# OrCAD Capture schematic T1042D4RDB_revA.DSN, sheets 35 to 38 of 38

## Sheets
35 35 Pwr Switch: size B
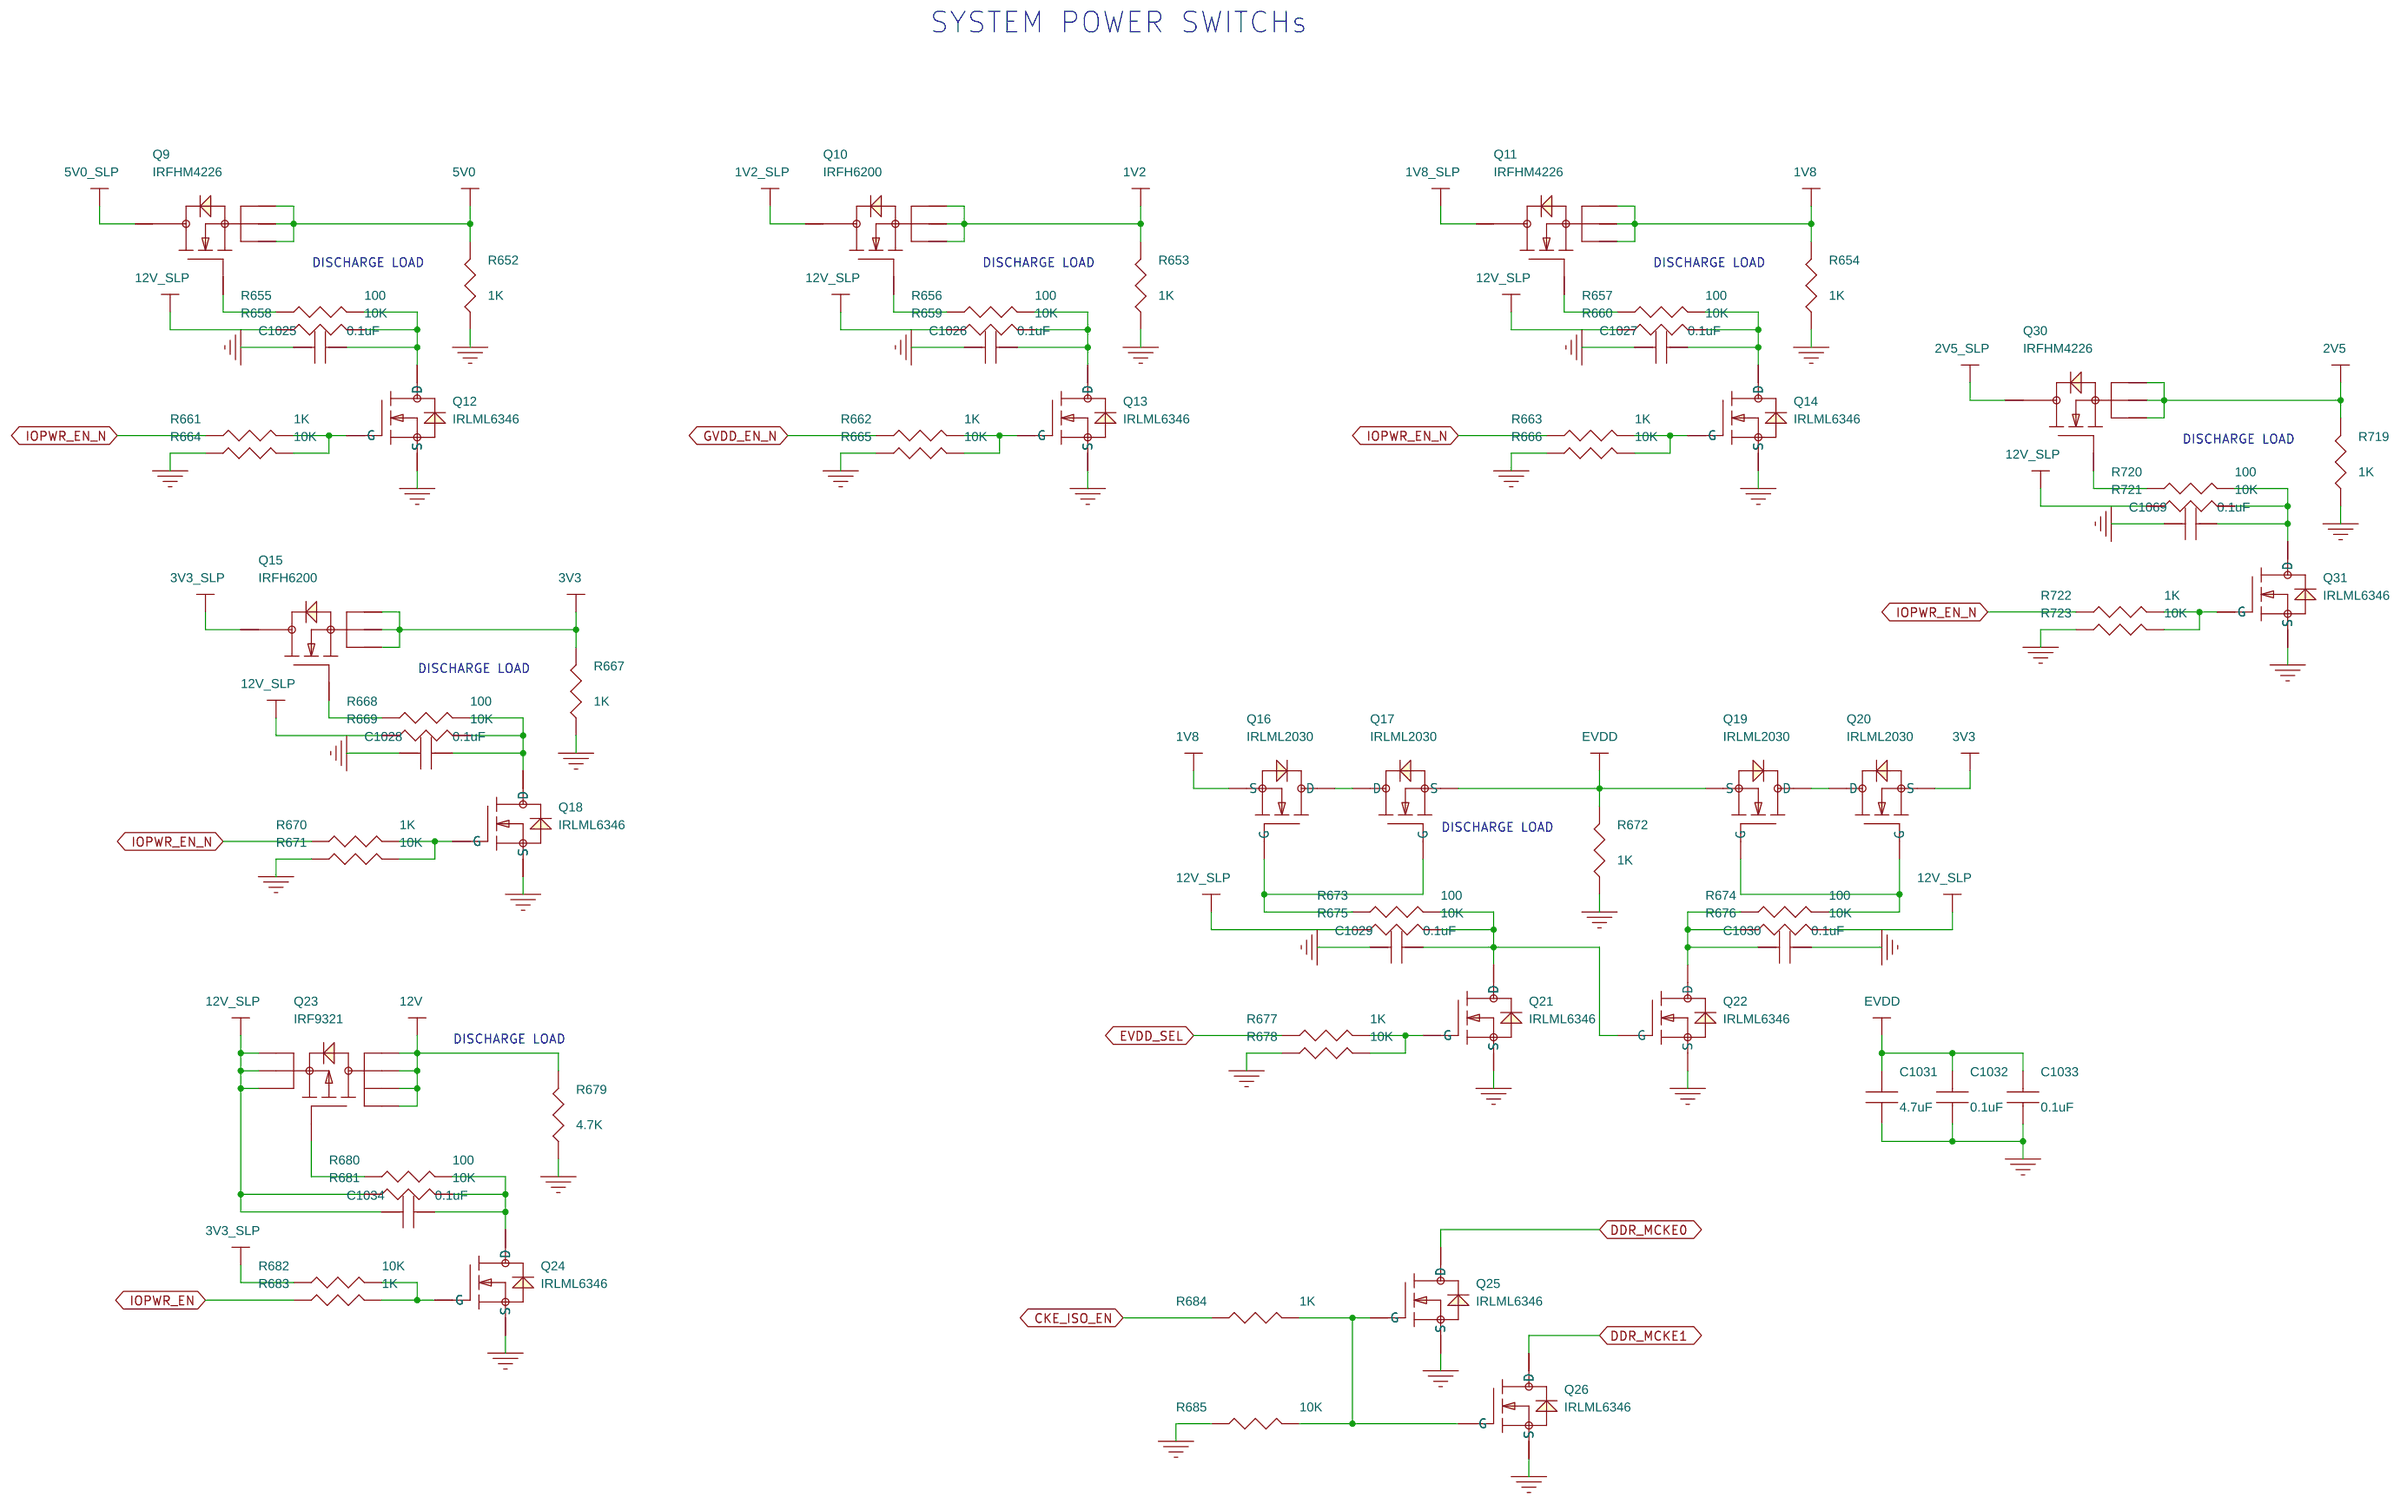
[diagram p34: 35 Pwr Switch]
36 36 Pwr In: size B
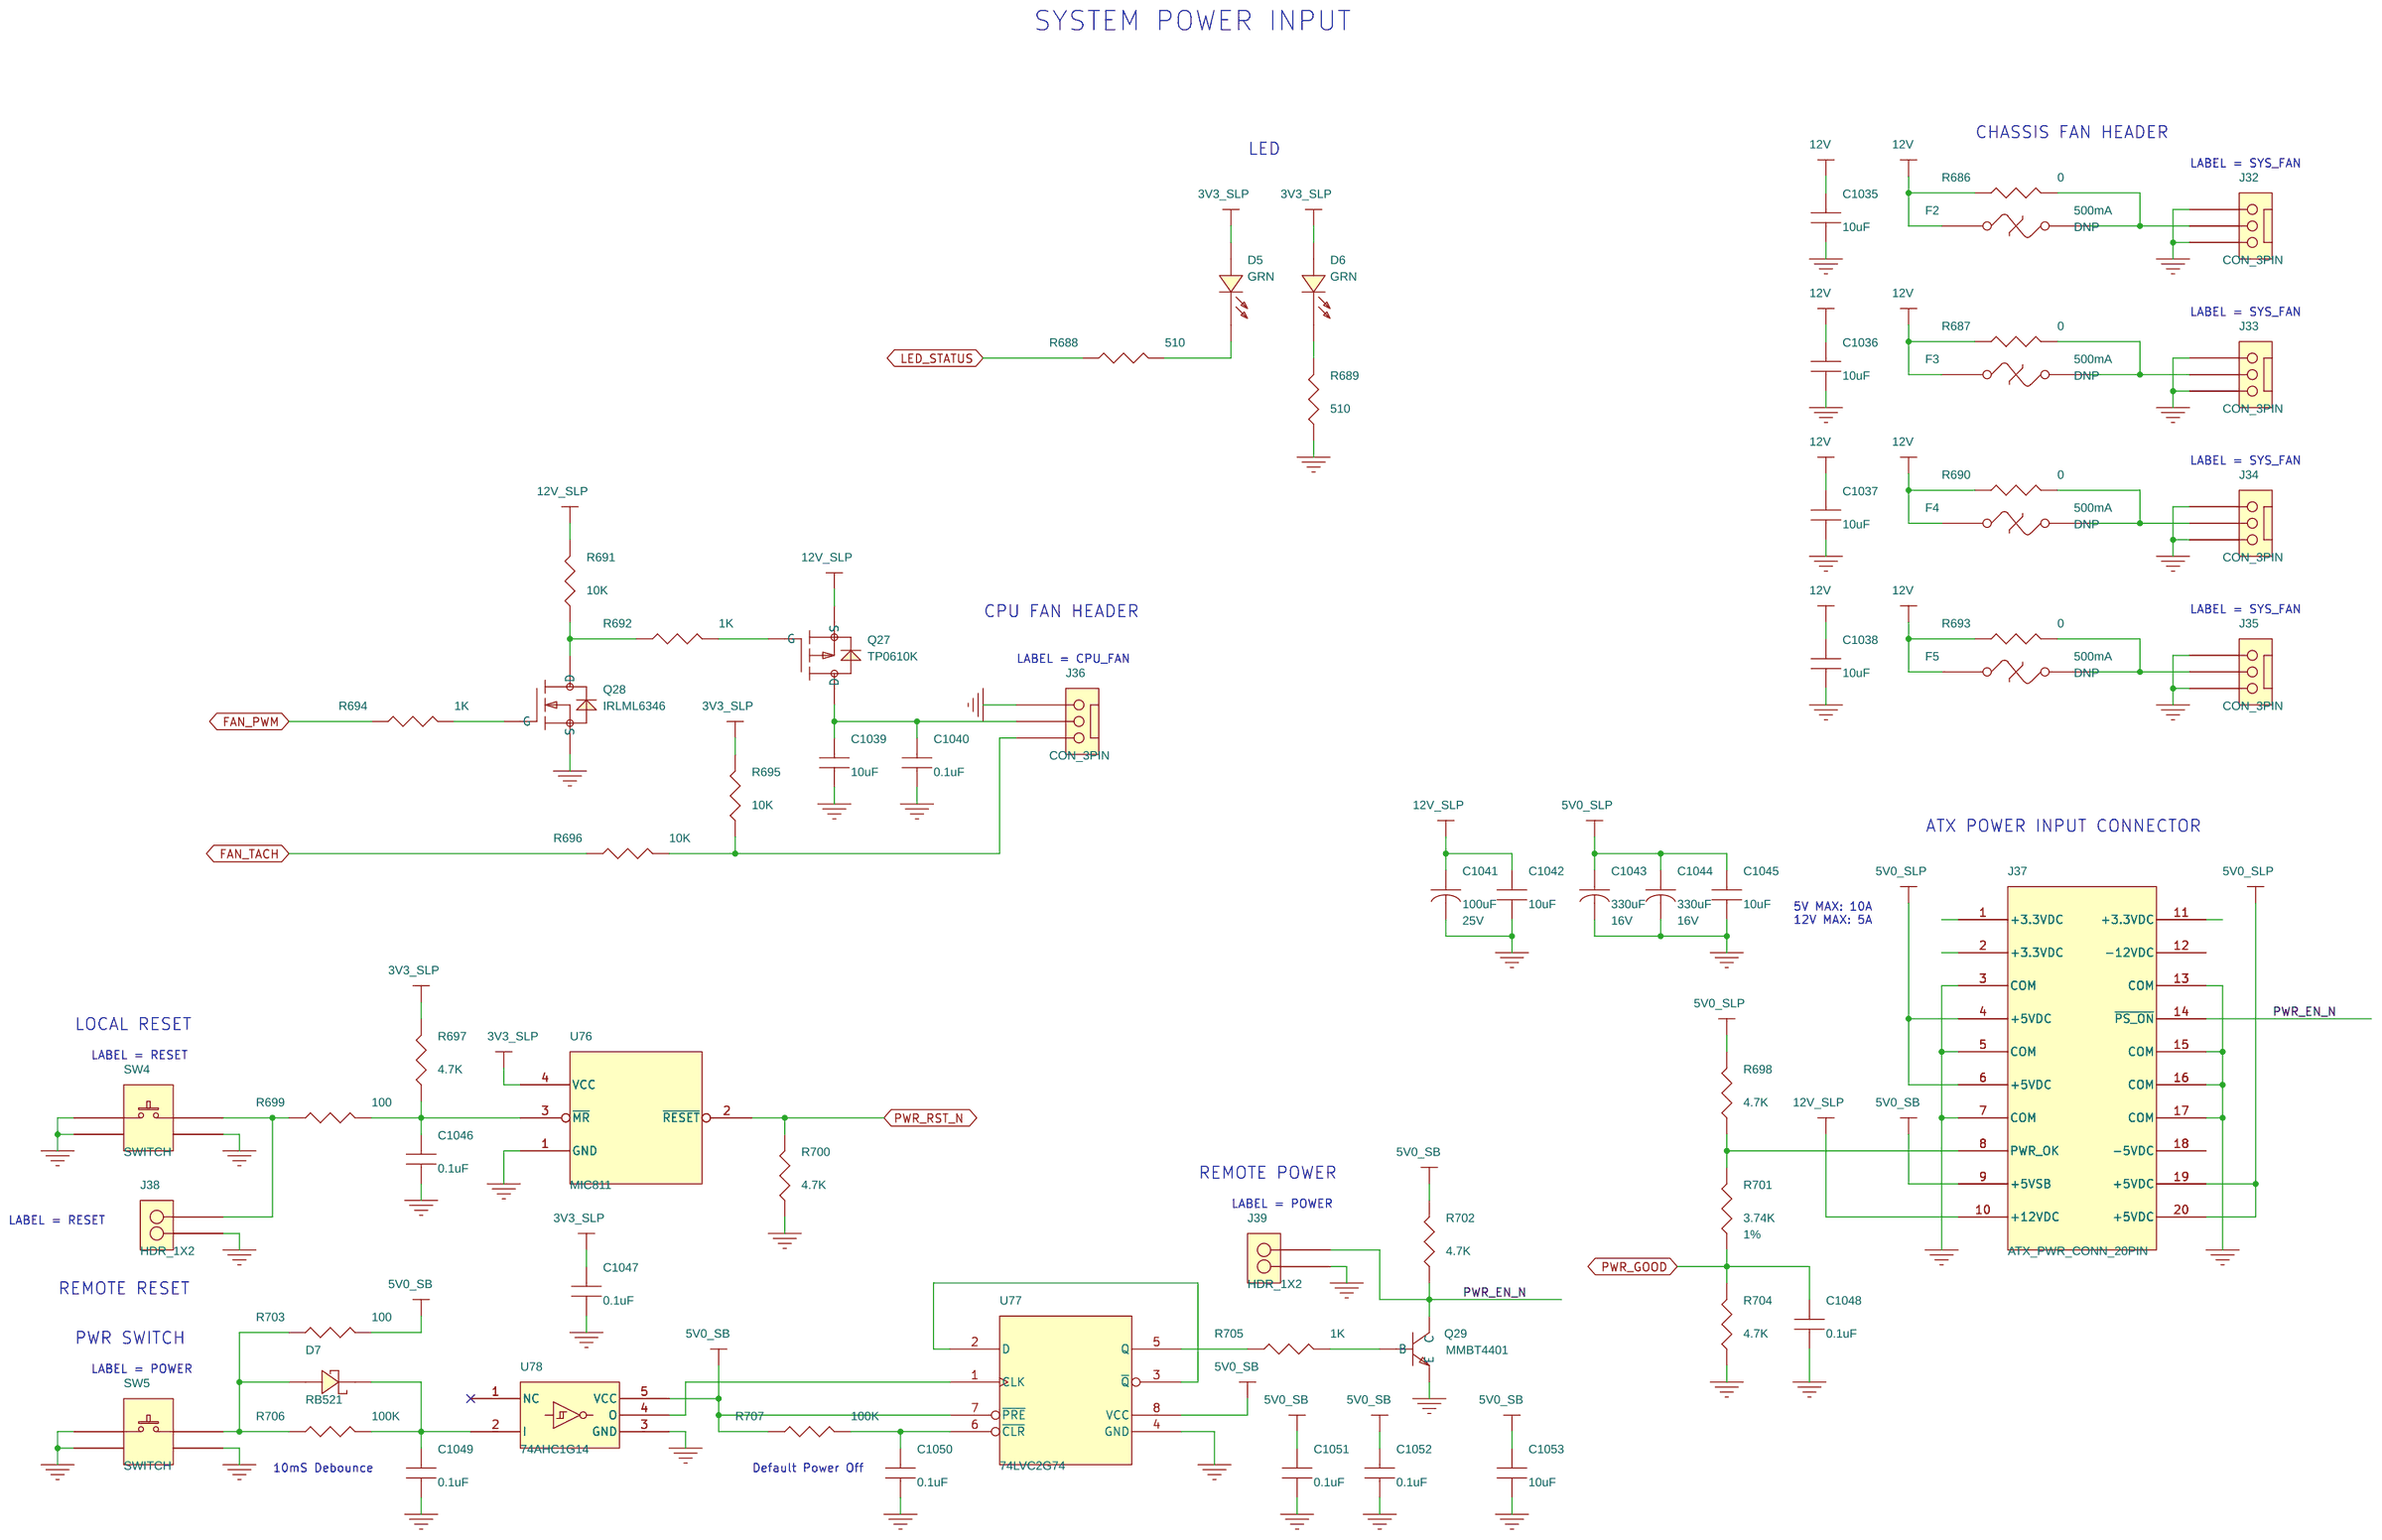
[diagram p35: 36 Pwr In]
37 37 MEC: size B
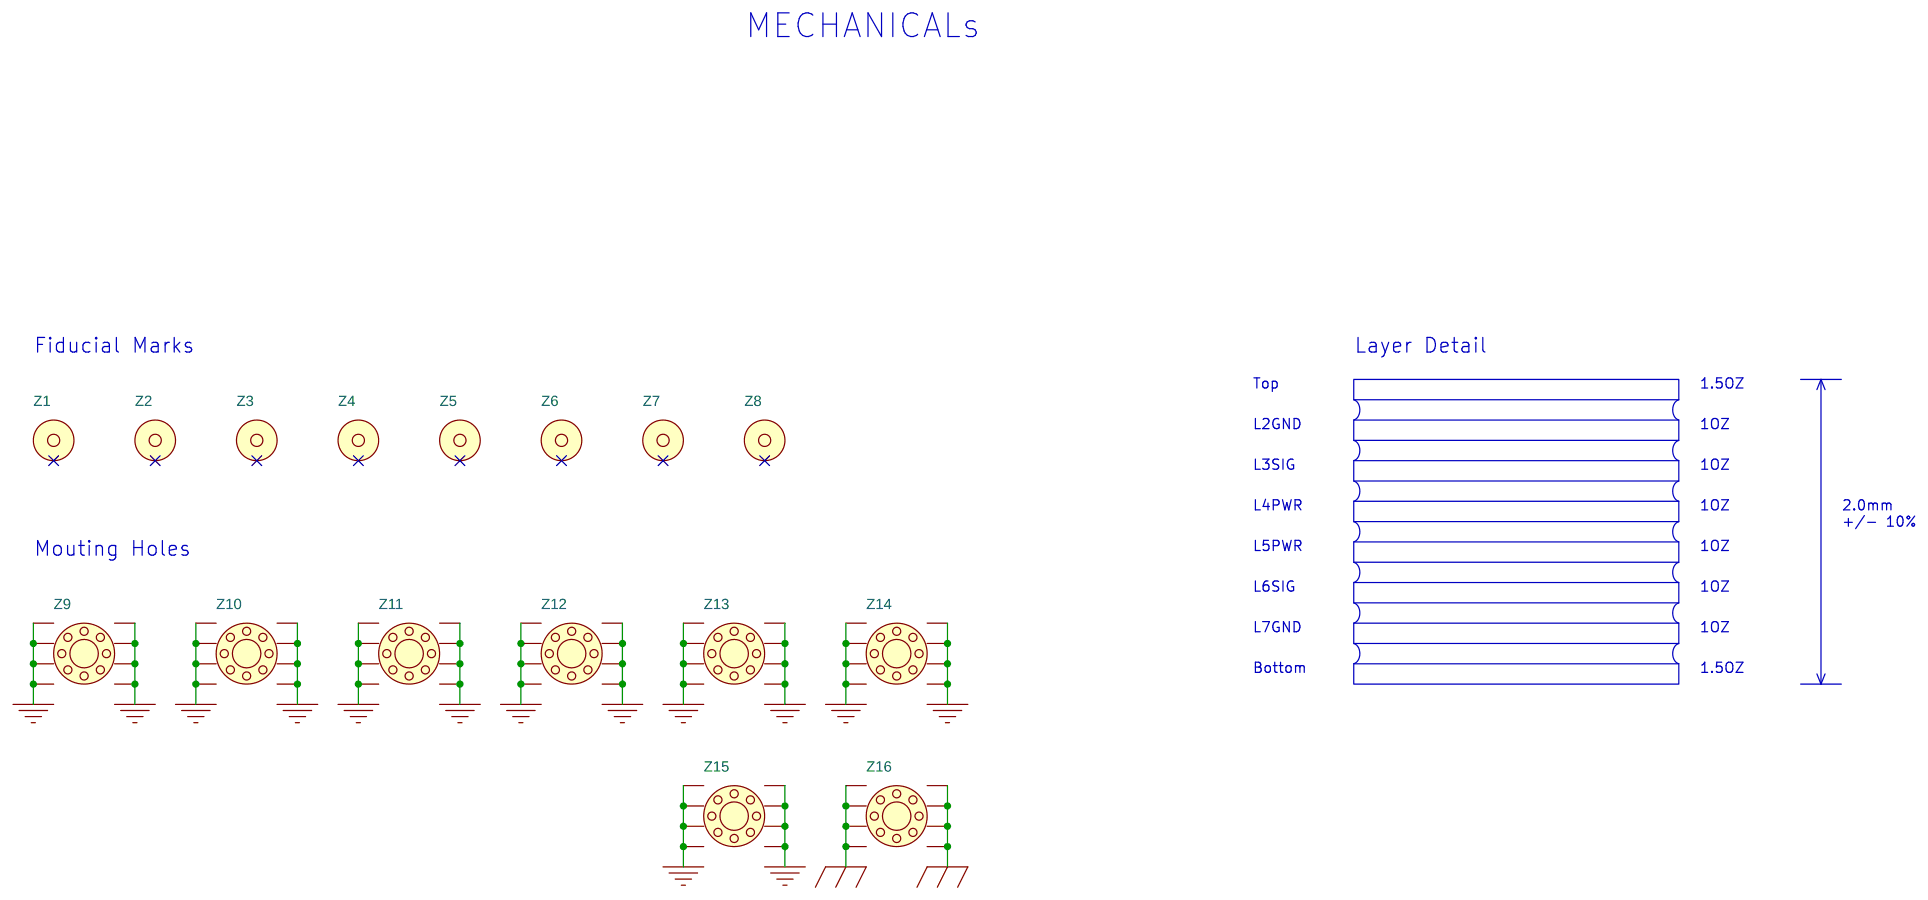
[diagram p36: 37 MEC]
38 38 Change List
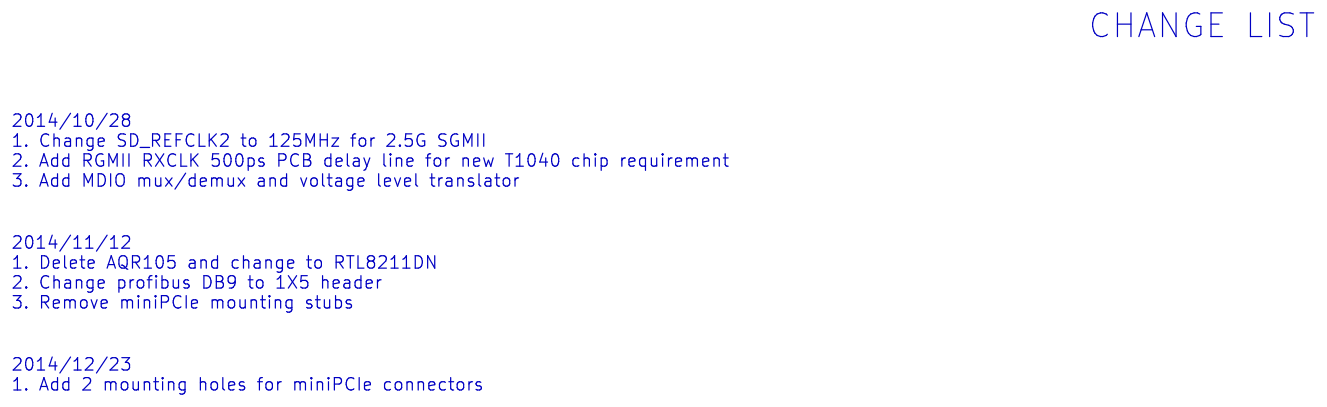
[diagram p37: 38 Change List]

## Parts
sheet 35 Pwr Switch
C1025  0.1uF  [0402]
C1026  0.1uF  [0402]
C1027  0.1uF  [0402]
C1028  0.1uF  [0402]
C1029  0.1uF  [0402]
C1030  0.1uF  [0402]
C1031  4.7uF  [0603]
C1032  0.1uF  [0402]
C1033  0.1uF  [0402]
C1034  0.1uF  [0402]
C1069  0.1uF  [0402]
Q9  IRFHM4226  [u8_fl]
Q10  IRFH6200  [so_8_fl]
Q11  IRFHM4226  [u8_fl]
Q12  IRLML6346  [sot23]
Q13  IRLML6346  [sot23]
Q14  IRLML6346  [sot23]
Q15  IRFH6200  [so_8_fl]
Q16  IRLML2030  [sot23]
Q17  IRLML2030  [sot23]
Q18  IRLML6346  [sot23]
Q19  IRLML2030  [sot23]
Q20  IRLML2030  [sot23]
Q21  IRLML6346  [sot23]
Q22  IRLML6346  [sot23]
Q23  IRF9321  [so_8]
Q24  IRLML6346  [sot23]
Q25  IRLML6346  [sot23]
Q26  IRLML6346  [sot23]
Q30  IRFHM4226  [u8_fl]
Q31  IRLML6346  [sot23]
R652  1K  [0402]
R653  1K  [0402]
R654  1K  [0402]
R655  100  [0402]
R656  100  [0402]
R657  100  [0402]
R658  10K  [0402]
R659  10K  [0402]
R660  10K  [0402]
R661  1K  [0402]
R662  1K  [0402]
R663  1K  [0402]
R664  10K  [0402]
R665  10K  [0402]
R666  10K  [0402]
R667  1K  [0402]
R668  100  [0402]
R669  10K  [0402]
R670  1K  [0402]
R671  10K  [0402]
R672  1K  [0402]
R673  100  [0402]
R674  100  [0402]
R675  10K  [0402]
R676  10K  [0402]
R677  1K  [0402]
R678  10K  [0402]
R679  4.7K  [0402]
R680  100  [0402]
R681  10K  [0402]
R682  10K  [0402]
R683  1K  [0402]
R684  1K  [0402]
R685  10K  [0402]
R719  1K  [0402]
R720  100  [0402]
R721  10K  [0402]
R722  1K  [0402]
R723  10K  [0402]
sheet 36 Pwr In
C1035  10uF  [1206]
C1036  10uF  [1206]
C1037  10uF  [1206]
C1038  10uF  [1206]
C1039  10uF  [1206]
C1040  0.1uF  [0603]
C1041  100uF  [cape_b6d3]
C1042  10uF  [1206]
C1043  330uF  [cape_b8]
C1044  330uF  [cape_b8]
C1045  10uF  [0805]
C1046  0.1uF  [0402]
C1047  0.1uF  [0402]
C1048  0.1uF  [0402]
C1049  0.1uF  [0402]
C1050  0.1uF  [0402]
C1051  0.1uF  [0402]
C1052  0.1uF  [0402]
C1053  10uF  [0805]
D5  GRN  [led_pm_1s]
D6  GRN  [led_pm_1s]
D7  RB521  [sod523]
F2  500mA  [1206]
F3  500mA  [1206]
F4  500mA  [1206]
F5  500mA  [1206]
J32  CON_3PIN  [con_wafer_p254_s_1x3]
J33  CON_3PIN  [con_wafer_p254_s_1x3]
J34  CON_3PIN  [con_wafer_p254_s_1x3]
J35  CON_3PIN  [con_wafer_p254_s_1x3]
J36  CON_3PIN  [con_wafer_p254_s_1x3]
J37  ATX_PWR_CONN_20PIN  [con_atx_20pin]
J38  HDR_1X2  [jmp_p254_t_1x2]
J39  HDR_1X2  [jmp_p254_t_1x2]
Q27  TP0610K  [sot23]
Q28  IRLML6346  [sot23]
Q29  MMBT4401  [sot23]
R686  0  [1206]
R687  0  [1206]
R688  510  [0402]
R689  510  [0402]
R690  0  [1206]
R691  10K  [0402]
R692  1K  [0402]
R693  0  [1206]
R694  1K  [0402]
R695  10K  [0402]
R696  10K  [0402]
R697  4.7K  [0402]
R698  4.7K  [0402]
R699  100  [0402]
R700  4.7K  [0402]
R701  3.74K  [0402]
R702  4.7K  [0402]
R703  100  [0402]
R704  4.7K  [0402]
R705  1K  [0402]
R706  100K  [0402]
R707  100K  [0402]
SW4  SWITCH  [con_sw_60x60_2p2_34]
SW5  SWITCH  [con_sw_60x60_2p2_34]
U76  MIC811  [sot143]
U77  74LVC2G74  [u8]
U78  74AHC1G14  [sc70_5]
sheet 37 MEC
Z1  FIDUCIAL  [fiducial]
Z2  FIDUCIAL  [fiducial]
Z3  FIDUCIAL  [fiducial]
Z4  FIDUCIAL  [fiducial]
Z5  FIDUCIAL  [fiducial]
Z6  FIDUCIAL  [fiducial]
Z7  FIDUCIAL  [fiducial]
Z8  FIDUCIAL  [fiducial]
Z9  MH_M8  [mh_900c400n_m]
Z10  MH_M8  [mh_900c400n_m]
Z11  MH_M8  [mh_900c400n_m]
Z12  MH_M8  [mh_900c400n_m]
Z13  MH_M8  [mh_900c400n_m]
Z14  MH_M8  [mh_900c400n_m]
Z15  MH_M8  [mh_900c400n_m]
Z16  MH_M8  [mh_900c400n_m]

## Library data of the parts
C1025-C1030 C1032-C1034 C1046-C1052 C1069 = CAP: VOLTAGE: 16V
C1031 = CAP: VOLTAGE: 6.3V
Q9 Q11 Q30 = NMOS_SO8FL: MPN: IRFHM4226TRPBF; TYPE: MOS; Vendor: IR
Q10 Q15 = NMOS_SO8FL: MPN: IRFH6200TRPBF; TYPE: MOS; Vendor: IR
Q12-Q14 Q18 Q21 Q22 Q24-Q26 Q28 Q31 = NMOS: MPN: IRLML6346TRPBF; TYPE: MOS; Vendor: IR
Q16 Q17 Q19 Q20 = NMOS: MPN: IRLML2030TRPBF; TYPE: MOS; Vendor: IR
Q23 = PMOS_SO8: MPN: IRF9321TRPBF; TYPE: MOS; Vendor: IR
R652-R700 R702-R707 R719-R723 = RES: TOL: 5%
C1035-C1040 C1042 = CAP: VOLTAGE: 25V
C1041 = CAP_E: TYPE: CAP; VOLTAGE: 25V
C1043 C1044 = CAP_E: TYPE: CAP; VOLTAGE: 16V
C1045 C1053 = CAP: VOLTAGE: 10V
D5 D6 = LED: MPN: L-96A8YVP/1GD/TG-0L; Vendor: Kingbrignt
D7 = DIODE_SCHOTTKY: MPN: RB521S30T1G; TYPE: DIODE; Vendor: ON Semi
F2-F5 = PTC: BOM_IGNORE: DNP; MPN: 1206L050; Vendor: Littelfuse
J32-J36 = CONN_3PIN: MPN: WRFB-DS03T2NNAX-X; TYPE: HDR; Vendor: SUPERIOR TECH
J37 = ATX_PWR_CONN_20PIN: MPN: 5566-20A; TYPE: CON; Vendor: MOLEX
J38 J39 = CONN_1X2: MPN: TSW-102-07-F-S; TYPE: HDR; Vendor: Samtec
Q27 = PMOS: TYPE: IC; Vendor: VISHAY
Q29 = TRANS_NPN: MPN: MMBT4401T-7-F; TYPE: TRAN; Vendor: DIODES
R701 = RES: TOL: 1%
SW4 SW5 = SWITCH_2P2: MPN: KFC-01-01-01-6*6*7; TYPE: CON; Vendor: UNIT
U76 = MAX811S: MPN: MIC811SUY; TYPE: IC; Vendor: Micrel
U77 = 74LVC2G74: MPN: SN74LVC2G74DCUR; TYPE: IC; Vendor: TI
U78 = 74LVC1G14: MPN: SN74AHC1G14DCKR; TYPE: IC; Vendor: TI
Z1-Z8 = FIDUCIAL: TYPE: PAD
Z9-Z16 = MH_M8: TYPE: PAD

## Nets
1V2: Q10.1 Q10.2 Q10.3 R653.2 ; also on sheet 3 12
1V2_SLP: Q10.5 ; also on sheet 3 13 33 34
1V8: Q11.1 Q11.2 Q11.3 Q16.2(S) R654.2 ; also on sheet 4 5 7 12 13 29 30
1V8_SLP: Q11.5 ; also on sheet 7 12 13 29 30 31 33 34
2V5: Q30.1 Q30.2 Q30.3 R719.2 ; also on sheet 8 12 20 21 22 23 24 25 26
2V5_SLP: Q30.5 ; also on sheet 7 8 12 19 33
3V3: Q15.1 Q15.2 Q15.3 Q20.2(S) R667.2 ; also on sheet 5 6 7 9 11 12 14 15 16 17 18 20 21 22 23 27 30
3V3_SLP: C1047.1 D5.2 D6.2 Q15.5 R682.1 R695.2 R697.2 U76.4(VCC) ; also on sheet 3 7 10 12 14 19 28 29 30 32 33 34
5V0: Q9.1 Q9.2 Q9.3 R652.2 ; also on sheet 16 18
5V0_SB: C1051.1 C1052.1 C1053.1 J37.9(+5VSB) R702.2 R703.2 R707.1 U77.7(~{PRE}) U77.8(VCC) U78.5(VCC)
5V0_SLP: C1043.1 C1044.1 C1045.1 J37.4(+5VDC) J37.6(+5VDC) J37.19(+5VDC) J37.20(+5VDC) Q9.5 R698.2 ; also on sheet 10 32 33
12V: C1035.1 C1036.1 C1037.1 C1038.1 F2.1 F3.1 F4.1 F5.1 Q23.5 Q23.6 Q23.7 Q23.8 R679.2 R686.1 R687.1 R690.1 R693.1 ; also on sheet 15 17 27
12V_SLP: C1034.1 C1041.1 C1042.1 J37.10(+12VDC) Q23.1 Q23.2 Q23.3 Q27.2(S) R658.1 R659.1 R660.1 R669.1 R675.1 R676.2 R681.1 R691.2 R721.1 ; also on sheet 32
-5VDC: J37.18(-5VDC)
-12VDC: J37.12(-12VDC)
GND: C1025.1 C1026.1 C1027.1 C1028.1 C1029.1 C1030.2 C1031.2 C1032.2 C1033.2 C1035.2 C1036.2 C1037.2 C1038.2 C1039.2 C1040.2 C1041.2 C1042.2 C1043.2 C1044.2 C1045.2 C1046.2 C1047.2 C1048.2 C1049.2 C1050.2 C1051.2 C1052.2 C1053.2 C1069.1 J32.1 J32.3 J33.1 J33.3 J34.1 J34.3 J35.1 J35.3 J36.3 J37.3(COM) J37.5(COM) J37.7(COM) J37.13(COM) J37.15(COM) J37.16(COM) J37.17(COM) J38.2 J39.2 Q12.2(S) Q13.2(S) Q14.2(S) Q18.2(S) Q21.2(S) Q22.2(S) Q24.2(S) Q25.2(S) Q26.2(S) Q28.2(S) Q29.2(E) Q31.2(S) R652.1 R653.1 R654.1 R664.1 R665.1 R666.1 R667.1 R671.1 R672.1 R678.1 R679.1 R685.1 R689.1 R700.1 R704.1 R719.1 R723.1 SW4.1 SW4.3 SW4.4 SW5.1 SW5.3 SW5.4 U76.1(GND) U77.4(GND) U78.3(GND) Z9.1 Z9.2 Z9.3 Z9.4 Z9.5 Z9.6 Z9.7 Z9.8 Z10.1 Z10.2 Z10.3 Z10.4 Z10.5 Z10.6 Z10.7 Z10.8 Z11.1 Z11.2 Z11.3 Z11.4 Z11.5 Z11.6 Z11.7 Z11.8 Z12.1 Z12.2 Z12.3 Z12.4 Z12.5 Z12.6 Z12.7 Z12.8 Z13.1 Z13.2 Z13.3 Z13.4 Z13.5 Z13.6 Z13.7 Z13.8 Z14.1 Z14.2 Z14.3 Z14.4 Z14.5 Z14.6 Z14.7 Z14.8 Z15.1 Z15.2 Z15.3 Z15.4 Z15.5 Z15.6 Z15.7 Z15.8 ; also on sheet 3 4 5 6 7 8 9 10 11 12 13 14 15 16 17 18 19 20 21 22 23 24 25 26 27 28 29 30 31 32 33 34
CKE_ISO_EN: R684.1 ; also on sheet 29
DDR_MCKE0: Q25.3(D) ; also on sheet 3
DDR_MCKE1: Q26.3(D) ; also on sheet 3
EARTH: Z16.1 Z16.2 Z16.3 Z16.4 Z16.5 Z16.6 Z16.7 Z16.8 ; also on sheet 10 14 16 19 20 21 22 23 26
EVDD: C1031.1 C1032.1 C1033.1 Q17.2(S) Q19.2(S) R672.2 ; also on sheet 6 12
EVDD_SEL: R677.1 ; also on sheet 29
FAN_PWM: R694.1 ; also on sheet 29
FAN_TACH: R696.1 ; also on sheet 29
GVDD_EN_N: R662.1 ; also on sheet 29
IOPWR_EN: R683.1 ; also on sheet 29 33
IOPWR_EN_N: R661.1 R663.1 R670.1 R722.1 ; also on sheet 29
LED_STATUS: R688.1 ; also on sheet 29
PWR_EN_N: J37.14(~{PS_ON}) J39.1 Q29.3(C) R702.1
PWR_GOOD: C1048.1 R701.1 R704.2 ; also on sheet 29
PWR_RST_N: R700.2 U76.2(~{RESET}) ; also on sheet 29
N17399246: C1046.1 R697.1 R699.2 U76.3(~{MR})
N17399288: J38.1 R699.1 SW4.2
N17400346: D7.2 R703.1 R706.1 SW5.2
N17401317: U77.1(CLK) U78.4(O)
N17401544: C1049.1 D7.1 R706.2 U78.2(I)
N17523688: U77.2(D) U77.3(~{Q})
N17523697: R705.1 U77.5(Q)
N17523706: C1050.1 R707.2 U77.6(~{CLR})
N17525004: Q28.3(D) R691.1 R692.1
N17596169: Q27.1(G) R692.2
N17596715: C1039.1 C1040.1 J36.2 Q27.3(D)
N17597092: J36.1 R695.1 R696.2
N17598342: Q28.1(G) R694.2
N17696036: Q12.1(G) R661.2 R664.2
N17696038: C1025.2 Q12.3(D) R655.2 R658.2
N17696060: Q9.4 R655.1
N17742094: C1034.2 Q24.3(D) R680.2 R681.2
N18177051: C1069.2 Q31.3(D) R720.2 R721.2
N18177053: Q31.1(G) R722.2 R723.2
N18177080: Q30.4 R720.1
N18275528: Q14.1(G) R663.2 R666.2
N18275529: C1027.2 Q14.3(D) R657.2 R660.2
N18275540: Q11.4 R657.1
N18275558: Q18.1(G) R670.2 R671.2
N18275559: C1028.2 Q18.3(D) R668.2 R669.2
N18275570: Q15.4 R668.1
N18275588: Q24.1(G) R682.2 R683.2
N18275595: Q23.4 R680.1
N18569886: Q29.1(B) R705.2
N18569887: J37.8(PWR_OK) R698.1 R701.2
N19623883: C1026.2 Q13.3(D) R656.2 R659.2
N19623885: Q13.1(G) R662.2 R665.2
N19623968: Q10.4 R656.1
N20553507: Q25.1(G) Q26.1(G) R684.2 R685.2
N20559490: Q21.1(G) R677.2 R678.2
N20559492: C1029.2 Q21.3(D) Q22.1(G) R673.2 R675.2
N20559589: Q16.1(G) Q17.1(G) R673.1
N20559634: Q16.3(D) Q17.3(D)
N20559669: C1030.1 Q22.3(D) R674.1 R676.1
N20559724: Q19.1(G) Q20.1(G) R674.2
N22360230: F2.2 J32.2 R686.2
N22360382: F3.2 J33.2 R687.2
N22360534: F4.2 J34.2 R690.2
N22361017: F5.2 J35.2 R693.2
N22361656: D5.1 R688.2
N22361689: D6.1 R689.2
N22440478: Q19.3(D) Q20.3(D)

Not connected (* = marked no-connect by the designer): J37 1(+3.3VDC) 2(+3.3VDC) 11(+3.3VDC); U78 1(NC)*; Z1 1*; Z2 1*; Z3 1*; Z4 1*; Z5 1*; Z6 1*; Z7 1*; Z8 1*

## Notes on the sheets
sheet 35
- SYSTEM POWER SWITCHs
- DISCHARGE LOAD
- DISCHARGE LOAD
- DISCHARGE LOAD
- DISCHARGE LOAD
- DISCHARGE LOAD
- DISCHARGE LOAD
- DISCHARGE LOAD
sheet 36
- SYSTEM POWER INPUT
- CHASSIS FAN HEADER
- LED
- LABEL = SYS_FAN
- LABEL = SYS_FAN
- LABEL = SYS_FAN
- CPU FAN HEADER
- LABEL = SYS_FAN
- LABEL = CPU_FAN
- ATX POWER INPUT CONNECTOR
- 5V MAX: 10A
  12V MAX: 5A
- LOCAL RESET
- LABEL = RESET
- REMOTE POWER
- LABEL = POWER
- LABEL = RESET
- REMOTE RESET
- PWR SWITCH
- LABEL = POWER
- 10mS Debounce
- Default Power Off
sheet 37
- MECHANICALs
- Fiducial Marks
- Layer Detail
- Top
- 1.5OZ
- L2GND
- 1OZ
- L3SIG
- 1OZ
- L4PWR
- 1OZ
- 2.0mm
  +/- 10%
- Mouting Holes
- L5PWR
- 1OZ
- L6SIG
- 1OZ
- L7GND
- 1OZ
- Bottom
- 1.5OZ
sheet 38
- CHANGE LIST
- 2014/10/28
  1. Change SD_REFCLK2 to 125MHz for 2.5G SGMII
  2. Add RGMII RXCLK 500ps PCB delay line for new T1040 chip requirement
  3. Add MDIO mux/demux and voltage level translator
- 2014/11/12
  1. Delete AQR105 and change to RTL8211DN
  2. Change profibus DB9 to 1X5 header
  3. Remove miniPCIe mounting stubs
- 2014/12/23
  1. Add 2 mounting holes for miniPCIe connectors
